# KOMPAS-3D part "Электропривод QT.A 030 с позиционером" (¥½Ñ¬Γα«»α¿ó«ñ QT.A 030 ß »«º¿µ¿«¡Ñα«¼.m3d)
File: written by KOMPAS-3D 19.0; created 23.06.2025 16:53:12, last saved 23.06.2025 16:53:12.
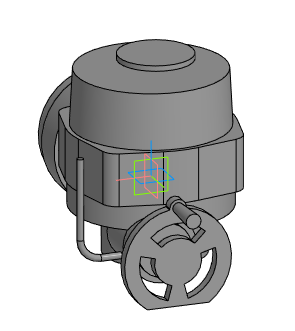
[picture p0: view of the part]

Document properties: Автор: Евгений; Полное имя файла: E:\Dendor Работа Сачек\3D для проектировщиков\3.5 Тип QT.А Электропривод\stp_Электропривод QT.A с позиционером\Электропривод QT.A 030 с позиционером.m3d

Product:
- Part/product: Электропривод QT.A 030 с позиционером

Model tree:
1. Операция без истории:1  (labels: Электропривод QT.A 030 с позиционером)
